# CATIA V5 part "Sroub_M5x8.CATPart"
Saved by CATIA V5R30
Part number: Sroub_M5x8
Definition: E 1200_5x8
Nomenclature: E 1200_5x8
Source: Unknown
Description: PART--DESC
Bounding box of the stored display mesh (mm): x -4.25 to 4.25, y -4.24 to 4.24, z 31.2 to 44.2
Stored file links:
  E:\Bakalarka\Model\Forma_v7\Sroub_M5x8.CATPart
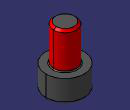
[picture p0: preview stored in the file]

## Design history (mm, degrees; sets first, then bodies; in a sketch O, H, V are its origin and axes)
Body1 "MANIFOLD_SOLID_BREP #3602" (main body)
  Solid1: solid without history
